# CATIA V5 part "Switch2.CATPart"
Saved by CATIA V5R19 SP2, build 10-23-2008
Part number: Switch
Definition: Switch
Nomenclature: Switch
Source: Unknown
Bounding box of the stored display mesh (mm): x -9 to 9, y -9 to 9, z -21.4 to 25.7
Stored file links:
  Z:\fausse table rondelle-20220905T211342Z-001\fausse table rondelle\Switch2.CATPart
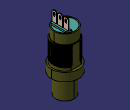
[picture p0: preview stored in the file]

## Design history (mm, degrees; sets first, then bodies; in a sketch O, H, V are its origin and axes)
AxisSystem1: origin (0, 0, 0), X (1, 0, 0), Y (0, 1, 0), Z (0, 0, 1)
Body1 "Switch" (main body)
  Solid1: solid without history
Body2 "Terminal 1"
  Solid2: solid without history
Body3 "Terminal 2"
  Solid3: solid without history
Body4 "Terminal 3"
  Solid4: solid without history
Body5 "Terminal Base connection"
  Solid5: solid without history
Body6 "Switch (1)"
  Solid6: solid without history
